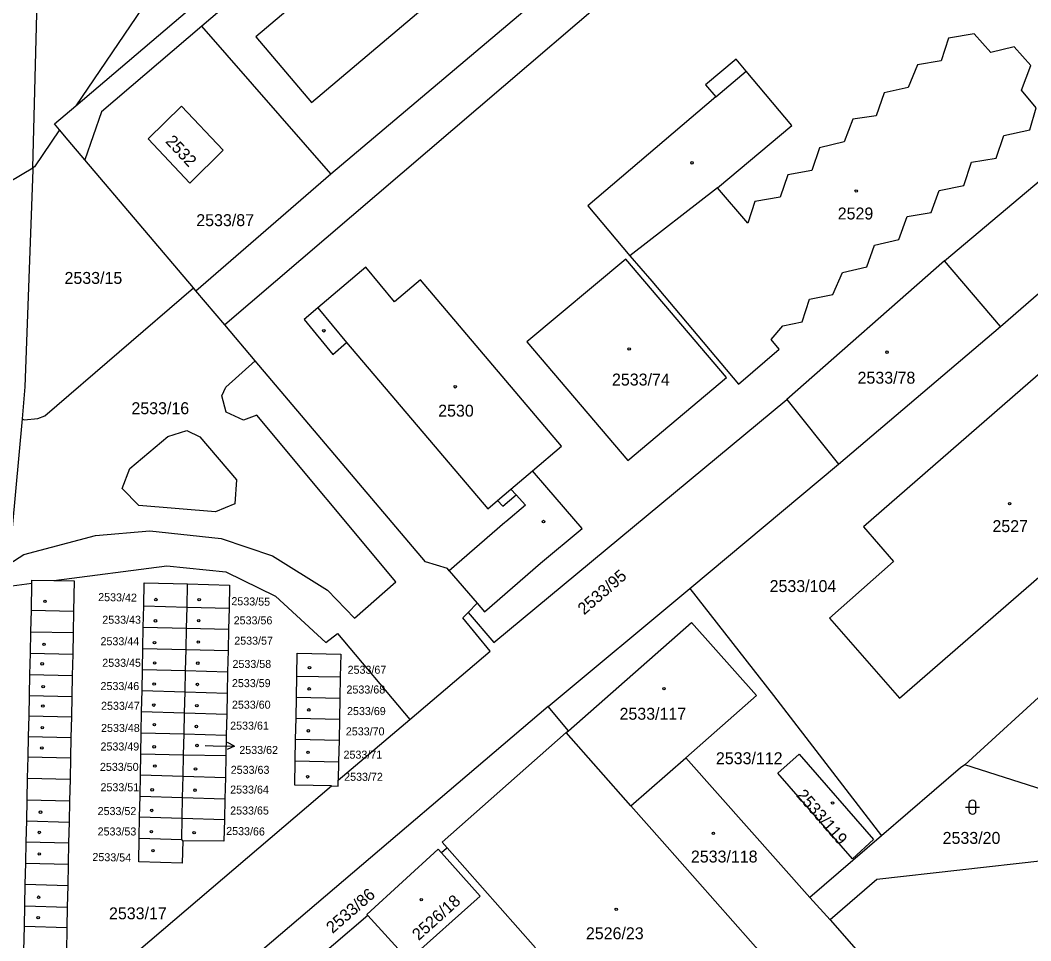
# Model space of a CAD drawing. Extents: x -527335 to -526256, y -1079142 to -1077809.
# Drawn here: x -527153.1 to -527009.3, y -1078313.2 to -1078182.2 of the extents above; entities that cross this region are included whole.
import ezdxf

# ---------------------------------------------------------------- set-up
doc = ezdxf.new("R2010")
doc.units = 0
for name, color, linetype in [('Vrstva 1', 7, 'Continuous'), ('Vrstva 2', 7, 'Continuous'), ('Vrstva 3', 7, 'Continuous'), ('Vrstva 4', 7, 'Continuous'), ('Vrstva 5', 7, 'Continuous'), ('Vrstva 7', 7, 'Continuous')]:
    doc.layers.add(name, color=color, linetype=linetype)

msp = doc.modelspace()

# ---------------------------------------------------------------- linework, layer by layer
at = {"layer": 'Vrstva 1'}
for p, q in [((-527145.19, -1078194.36), (-527021.08, -1078088.59)), ((-527075.98, -1078139.33), (-527127.29, -1078183.04)), ((-527108.95, -1078204.05), (-527057.85, -1078160.95)), ((-527108.95, -1078204.05), (-527127.29, -1078183.04)), ((-527021.59, -1078216.44), (-526994.58, -1078193.61)), ((-527128.49, -1078220.29), (-527143.91, -1078202.08)), ((-527013.64, -1078225.78), (-526986.9, -1078202.54)), ((-527168.74, -1078213.47), (-527151.32, -1078203.19)), ((-527128.12, -1078220.72), (-527108.95, -1078204.05)), ((-527021.59, -1078216.44), (-527044.03, -1078236.19)), ((-527013.64, -1078225.78), (-527021.59, -1078216.44)), ((-527128.12, -1078220.72), (-527128.49, -1078220.29)), ((-527124.03, -1078225.56), (-527128.12, -1078220.72)), ((-527036.7, -1078245.38), (-527013.64, -1078225.78)), ((-527018.73, -1078288.14), (-526960.09, -1078234.62)), ((-527044.03, -1078236.19), (-527036.7, -1078245.38)), ((-527057.86, -1078263.05), (-527036.7, -1078245.38)), ((-527092.08, -1078260.53), (-527088.09, -1078265.17)), ((-527155.03, -1078262.79), (-527151.46, -1078262.32)), ((-527151.54, -1078266.16), (-527151.46, -1078262.32)), ((-527129.38, -1078265.72), (-527129.3, -1078262.42)), ((-527078.01, -1078279.88), (-527057.86, -1078263.05)), ((-527135.61, -1078268.58), (-527135.55, -1078265.55)), ((-527135.55, -1078265.55), (-527129.38, -1078265.72)), ((-527129.45, -1078268.72), (-527129.38, -1078265.72)), ((-527129.38, -1078265.72), (-527123.41, -1078265.88)), ((-527123.41, -1078265.88), (-527123.48, -1078268.86)), ((-527089.37, -1078266.47), (-527088.09, -1078265.17)), ((-527151.61, -1078269.21), (-527151.54, -1078266.16)), ((-527151.54, -1078266.16), (-527145.52, -1078266.29)), ((-527145.52, -1078266.29), (-527145.59, -1078269.35)), ((-527135.67, -1078271.6), (-527135.61, -1078268.58)), ((-527135.61, -1078268.58), (-527129.45, -1078268.72)), ((-527129.52, -1078271.76), (-527129.45, -1078268.72)), ((-527129.45, -1078268.72), (-527123.48, -1078268.86)), ((-527123.48, -1078268.86), (-527123.54, -1078271.91)), ((-527151.68, -1078272.29), (-527151.61, -1078269.21)), ((-527151.61, -1078269.21), (-527145.59, -1078269.35)), ((-527145.59, -1078269.35), (-527145.65, -1078272.43)), ((-527135.73, -1078274.57), (-527135.67, -1078271.6)), ((-527135.67, -1078271.6), (-527129.52, -1078271.76)), ((-527129.59, -1078274.74), (-527129.52, -1078271.76)), ((-527129.52, -1078271.76), (-527123.54, -1078271.91)), ((-527123.54, -1078271.91), (-527123.61, -1078274.91)), ((-527151.75, -1078275.29), (-527151.68, -1078272.29)), ((-527151.68, -1078272.29), (-527145.65, -1078272.43)), ((-527145.65, -1078272.43), (-527145.72, -1078275.44)), ((-527135.79, -1078277.57), (-527135.73, -1078274.57)), ((-527135.73, -1078274.57), (-527129.59, -1078274.74)), ((-527129.66, -1078277.76), (-527129.59, -1078274.74)), ((-527129.59, -1078274.74), (-527123.61, -1078274.91)), ((-527151.81, -1078278.3), (-527151.75, -1078275.29)), ((-527151.75, -1078275.29), (-527145.72, -1078275.44)), ((-527145.72, -1078275.44), (-527145.78, -1078278.45)), ((-527123.61, -1078274.91), (-527123.67, -1078277.94)), ((-527113.83, -1078278.55), (-527113.78, -1078275.52)), ((-527113.78, -1078275.52), (-527107.58, -1078275.66)), ((-527107.58, -1078275.66), (-527107.64, -1078278.68)), ((-527135.85, -1078280.57), (-527135.79, -1078277.57)), ((-527135.79, -1078277.57), (-527129.66, -1078277.76)), ((-527151.87, -1078281.17), (-527151.81, -1078278.3)), ((-527151.81, -1078278.3), (-527145.78, -1078278.45)), ((-527145.78, -1078278.45), (-527145.84, -1078281.32)), ((-527129.73, -1078280.76), (-527129.66, -1078277.76)), ((-527129.66, -1078277.76), (-527123.67, -1078277.94)), ((-527123.67, -1078277.94), (-527123.74, -1078280.95)), ((-527113.88, -1078281.54), (-527113.83, -1078278.55)), ((-527113.83, -1078278.55), (-527107.64, -1078278.68)), ((-527107.64, -1078278.68), (-527107.7, -1078281.67)), ((-527075.11, -1078283.3), (-527078.01, -1078279.88)), ((-527151.94, -1078284.13), (-527151.87, -1078281.17)), ((-527151.87, -1078281.17), (-527145.84, -1078281.32)), ((-527145.84, -1078281.32), (-527145.91, -1078284.29)), ((-527135.9, -1078283.62), (-527135.85, -1078280.57)), ((-527135.85, -1078280.57), (-527129.73, -1078280.76)), ((-527129.8, -1078283.77), (-527129.73, -1078280.76)), ((-527129.73, -1078280.76), (-527123.74, -1078280.95)), ((-527123.74, -1078280.95), (-527123.8, -1078283.92)), ((-527113.94, -1078284.52), (-527113.88, -1078281.54)), ((-527113.88, -1078281.54), (-527107.7, -1078281.67)), ((-527107.87, -1078290.35), (-527097.7, -1078281.69)), ((-527107.7, -1078281.67), (-527107.76, -1078284.66)), ((-527075.43, -1078283.58), (-527075.11, -1078283.3)), ((-527152, -1078287), (-527151.94, -1078284.13)), ((-527151.94, -1078284.13), (-527145.91, -1078284.29)), ((-527145.91, -1078284.29), (-527145.97, -1078287.16)), ((-527135.96, -1078286.61), (-527135.9, -1078283.62)), ((-527135.9, -1078283.62), (-527129.8, -1078283.77)), ((-527129.87, -1078286.72), (-527129.8, -1078283.77)), ((-527129.8, -1078283.77), (-527123.8, -1078283.92)), ((-527123.8, -1078283.92), (-527123.87, -1078286.82)), ((-527113.99, -1078287.59), (-527113.94, -1078284.52)), ((-527113.94, -1078284.52), (-527107.76, -1078284.66)), ((-527107.76, -1078284.66), (-527107.82, -1078287.72)), ((-527066.22, -1078294.01), (-527075.43, -1078283.58)), ((-527152.07, -1078290.04), (-527152, -1078287)), ((-527152, -1078287), (-527145.97, -1078287.16)), ((-527145.97, -1078287.16), (-527146.03, -1078290.2)), ((-527136.02, -1078289.59), (-527135.96, -1078286.61)), ((-527135.96, -1078286.61), (-527129.87, -1078286.72)), ((-527129.94, -1078289.78), (-527129.87, -1078286.72)), ((-527129.87, -1078286.72), (-527123.87, -1078286.82)), ((-527123.87, -1078286.82), (-527123.93, -1078289.96)), ((-527113.99, -1078287.59), (-527107.82, -1078287.72)), ((-527107.82, -1078287.72), (-527107.87, -1078290.35)), ((-527066.22, -1078294.01), (-527058.42, -1078287.16)), ((-527058.42, -1078287.16), (-527040.76, -1078307.03)), ((-527152.14, -1078293.13), (-527152.07, -1078290.04)), ((-527152.07, -1078290.04), (-527146.03, -1078290.2)), ((-527146.03, -1078290.2), (-527146.1, -1078293.3)), ((-527136.08, -1078292.63), (-527136.02, -1078289.59)), ((-527136.02, -1078289.59), (-527129.94, -1078289.78)), ((-527130.01, -1078292.81), (-527129.94, -1078289.78)), ((-527129.94, -1078289.78), (-527123.93, -1078289.96)), ((-527123.93, -1078289.96), (-527124, -1078292.98)), ((-527152.2, -1078296.14), (-527152.14, -1078293.13)), ((-527152.14, -1078293.13), (-527146.1, -1078293.3)), ((-527146.1, -1078293.3), (-527146.16, -1078296.31)), ((-527136.14, -1078295.56), (-527136.08, -1078292.63)), ((-527136.08, -1078292.63), (-527130.01, -1078292.81)), ((-527130.08, -1078295.75), (-527130.01, -1078292.81)), ((-527130.01, -1078292.81), (-527124, -1078292.98)), ((-527124, -1078292.98), (-527124.06, -1078295.93)), ((-527152.27, -1078299.1), (-527152.2, -1078296.14)), ((-527152.2, -1078296.14), (-527146.16, -1078296.31)), ((-527146.16, -1078296.31), (-527146.23, -1078299.27)), ((-527136.19, -1078298.58), (-527136.14, -1078295.56)), ((-527136.14, -1078295.56), (-527130.08, -1078295.75)), ((-527130.15, -1078298.8), (-527130.08, -1078295.75)), ((-527130.08, -1078295.75), (-527124.06, -1078295.93)), ((-527152.34, -1078302.13), (-527152.27, -1078299.1)), ((-527152.27, -1078299.1), (-527146.23, -1078299.27)), ((-527136.19, -1078298.58), (-527130.15, -1078298.8)), ((-527129.99, -1078298.98), (-527130.15, -1078298.8)), ((-527030.55, -1078298.24), (-527040.76, -1078307.03)), ((-527146.23, -1078299.27), (-527146.29, -1078302.31)), ((-527079.8, -1078314.2), (-527092.36, -1078299.98)), ((-527152.4, -1078305.13), (-527152.34, -1078302.13)), ((-527152.34, -1078302.13), (-527146.29, -1078302.31)), ((-527146.29, -1078302.31), (-527146.36, -1078305.31)), ((-527152.47, -1078308.23), (-527152.4, -1078305.13)), ((-527152.4, -1078305.13), (-527146.36, -1078305.31)), ((-527146.36, -1078305.31), (-527146.42, -1078308.41)), ((-527040.76, -1078307.03), (-527037.9, -1078310.24)), ((-527152.53, -1078311.13), (-527152.47, -1078308.23)), ((-527152.47, -1078308.23), (-527146.42, -1078308.41)), ((-527146.42, -1078308.41), (-527146.49, -1078311.32)), ((-527152.53, -1078311.13), (-527146.49, -1078311.32))]:
    msp.add_line(p, q, dxfattribs=at)
for points in [[(-527151.32, -1078203.19), (-527149.15, -1078119.04), (-527147.89, -1078077.9), (-527146.9, -1078035.16), (-527147.21, -1078003.19)], [(-527021.08, -1078088.59), (-527032.67, -1078087.91), (-527048.92, -1078102.61), (-527126.32, -1078166.52), (-527145.19, -1078194.36)], [(-526994.58, -1078193.61), (-526995.55, -1078180.16), (-527023.46, -1078146.11), (-527026.79, -1078144.7), (-527030.6, -1078145.62), (-527124.03, -1078225.56)], [(-527073.25, -1078145.36), (-527119.6, -1078184.54), (-527111.69, -1078193.91), (-527065.33, -1078154.73), (-527073.25, -1078145.36)], [(-527127.29, -1078183.04), (-527141.57, -1078195.21), (-527143.91, -1078202.08)], [(-527018.88, -1078205.71), (-527017.76, -1078202.41), (-527014.28, -1078201.83), (-527013.18, -1078198.6), (-527009.48, -1078197.8), (-527008.56, -1078194.68), (-527010.67, -1078192.13), (-527009.31, -1078188.63), (-527011.7, -1078185.99), (-527015.02, -1078186.78), (-527017.41, -1078184.14), (-527021.05, -1078184.77), (-527022.1, -1078187.99), (-527025.47, -1078188.54), (-527026.77, -1078191.79), (-527030.19, -1078192.53), (-527031.34, -1078195.8), (-527034.66, -1078196.29), (-527035.89, -1078199.51), (-527039.38, -1078200.37), (-527040.49, -1078203.56), (-527043.9, -1078204.19), (-527044.98, -1078207.4), (-527048.61, -1078208), (-527049.6, -1078211.09), (-527053.92, -1078206.07), (-527043.32, -1078197.16), (-527049.81, -1078189.45), (-527051.27, -1078187.72), (-527055.6, -1078191.37), (-527054.14, -1078193.1), (-527072.36, -1078208.61), (-527066.4, -1078215.71), (-527063.27, -1078219.32), (-527050.92, -1078233.97), (-527045.12, -1078229.03), (-527046.26, -1078227.64), (-527044.59, -1078225.71), (-527041.86, -1078225.11), (-527040.83, -1078221.89), (-527037.48, -1078221.21), (-527036.11, -1078218.11), (-527032.68, -1078217.29), (-527031.57, -1078214.19), (-527028.13, -1078213.4), (-527026.91, -1078210.12), (-527023.49, -1078209.55), (-527022.35, -1078206.41), (-527018.88, -1078205.71)], [(-527147.53, -1078197.81), (-527148.24, -1078196.96), (-527145.19, -1078194.36)], [(-527130.16, -1078194.44), (-527134.92, -1078199.06), (-527128.97, -1078205.37), (-527124.24, -1078200.67), (-527130.16, -1078194.44)], [(-527147.53, -1078197.81), (-527151.07, -1078203.04), (-527151.32, -1078203.19)], [(-527143.91, -1078202.08), (-527146.31, -1078199.25), (-527147.53, -1078197.81)], [(-527151.32, -1078203.19), (-527151.33, -1078203.5), (-527152.45, -1078234.37), (-527152.87, -1078238.94)], [(-527066.97, -1078216.19), (-527081.03, -1078227.97), (-527066.68, -1078244.84), (-527052.61, -1078233.06), (-527066.97, -1078216.19)], [(-527088.09, -1078265.17), (-527087.05, -1078266.38), (-527079.07, -1078259.48), (-527073.18, -1078254.52), (-527078.17, -1078248.69), (-527080.22, -1078246.3), (-527076.09, -1078242.8), (-527096.17, -1078219.13), (-527099.86, -1078222.26), (-527103.94, -1078217.32), (-527110.79, -1078223.12), (-527112.74, -1078224.77), (-527108.62, -1078229.78), (-527106.7, -1078228.08), (-527086.6, -1078251.71), (-527085.21, -1078250.53), (-527084.47, -1078251.37), (-527082.56, -1078249.74), (-527081.22, -1078251.23), (-527084.03, -1078253.58), (-527084.16, -1078253.69), (-527092.08, -1078260.53)], [(-527152.87, -1078238.94), (-527152.57, -1078239.08), (-527150.64, -1078238.89), (-527149.6, -1078238.5), (-527128.49, -1078220.29)], [(-527092.08, -1078260.53), (-527092.34, -1078260.22), (-527095.48, -1078259.26), (-527119.71, -1078230.66), (-527124.03, -1078225.56)], [(-527028.01, -1078278.65), (-526982.22, -1078238.91), (-526992.1, -1078227.53), (-527001.43, -1078235.36), (-527005.72, -1078230.41), (-527033.14, -1078254.27), (-527028.87, -1078259.23), (-527037.98, -1078267.3), (-527028.01, -1078278.65)], [(-527089.37, -1078266.47), (-527085.73, -1078270.77), (-527044.03, -1078236.19)], [(-527152.87, -1078238.94), (-527154.74, -1078259.62), (-527154.85, -1078260.85)], [(-527148.36, -1078261.92), (-527132.28, -1078259.83), (-527123.87, -1078260.69), (-527116.82, -1078264.18), (-527109.65, -1078270.74), (-527107.97, -1078269.47), (-527097.7, -1078281.69)], [(-527151.46, -1078262.32), (-527151.45, -1078261.88), (-527148.36, -1078261.92)], [(-527148.36, -1078261.92), (-527145.43, -1078261.96), (-527145.52, -1078266.29)], [(-527135.55, -1078265.55), (-527135.49, -1078262.25), (-527129.3, -1078262.42)], [(-527129.3, -1078262.42), (-527123.34, -1078262.59), (-527123.41, -1078265.88)], [(-527057.86, -1078263.05), (-527045.96, -1078278.29), (-527030.55, -1078298.24)], [(-527097.7, -1078281.69), (-527086.26, -1078271.99), (-527090.15, -1078267.26), (-527089.37, -1078266.47)], [(-527075.11, -1078283.3), (-527057.6, -1078267.89), (-527048.34, -1078278.31), (-527058.42, -1078287.16)], [(-527113.78, -1078275.52), (-527113.72, -1078272.27), (-527107.51, -1078272.43), (-527107.58, -1078275.66)], [(-527078.01, -1078279.88), (-527149.04, -1078340.4), (-527152.71, -1078341.14), (-527153.16, -1078344.42), (-527154.22, -1078350.96), (-527154.21, -1078352.81)], [(-527092.36, -1078299.98), (-527093.08, -1078299.16), (-527075.43, -1078283.58)], [(-527108.84, -1078291.17), (-527114.05, -1078291.06), (-527113.99, -1078287.59)], [(-527031.69, -1078298.77), (-527034.72, -1078301.52), (-527045.34, -1078289.33), (-527042.31, -1078286.66), (-527031.69, -1078298.77)], [(-527018.73, -1078288.14), (-527019.33, -1078288.58), (-527030.55, -1078298.24)], [(-526991.13, -1078293.46), (-526996.39, -1078293.96), (-526999.54, -1078294.26), (-527018.73, -1078288.14)], [(-527108.84, -1078291.17), (-527107.89, -1078291.19), (-527107.87, -1078290.35)], [(-527157.99, -1078333.04), (-527157.02, -1078332.22), (-527108.84, -1078291.17)], [(-527041.68, -1078321.81), (-527061.79, -1078299.03), (-527066.22, -1078294.01)], [(-527124.06, -1078295.93), (-527124.13, -1078299.02), (-527129.99, -1078298.98)], [(-527129.99, -1078298.98), (-527130.08, -1078302.17), (-527136.26, -1078301.98), (-527136.19, -1078298.58)], [(-527093.17, -1078300.67), (-527093.64, -1078300.14), (-527103.79, -1078309.46), (-527103.65, -1078309.62)], [(-527092.36, -1078299.98), (-527092.46, -1078300.07), (-527093.17, -1078300.67)], [(-527093.17, -1078300.67), (-527087.7, -1078306.87), (-527097.86, -1078315.97), (-527103.65, -1078309.62)], [(-527000.09, -1078301), (-527004.9, -1078305.04), (-527006.83, -1078302.75), (-527007.63, -1078301.84), (-527031.23, -1078304.49), (-527037.9, -1078310.24)], [(-527103.65, -1078309.62), (-527113.42, -1078317.97), (-527124.23, -1078327.2)], [(-527037.9, -1078310.24), (-527033.83, -1078314.82), (-527041.68, -1078321.81)], [(-527146.49, -1078311.32), (-527146.56, -1078314.81), (-527152.61, -1078314.62), (-527152.53, -1078311.13)]]:
    msp.add_lwpolyline(points, dxfattribs=at)
at = {"layer": 'Vrstva 3'}
for p, q in [((-527018.63, -1078294.18), (-527016.63, -1078294.18)), ((-527018.13, -1078293.68), (-527018.13, -1078294.68)), ((-527017.13, -1078294.68), (-527017.13, -1078293.68))]:
    msp.add_line(p, q, dxfattribs=at)
for centre, start, end in [((-527017.63, -1078293.68), 0, 180), ((-527017.63, -1078294.68), 180, 359.9879)]:
    msp.add_arc(centre, 0.5, start, end, dxfattribs=at)
at = {"layer": 'Vrstva 4'}
for p, q in [((-527054.14, -1078193.1), (-527049.81, -1078189.45)), ((-527053.92, -1078206.07), (-527066.4, -1078215.71)), ((-527110.79, -1078223.12), (-527106.7, -1078228.08)), ((-527123.89, -1078234.43), (-527119.71, -1078230.66)), ((-527124.43, -1078235.67), (-527123.89, -1078234.43)), ((-527123.84, -1078237.98), (-527124.43, -1078235.67)), ((-527121.35, -1078239.1), (-527123.84, -1078237.98)), ((-527119.46, -1078238.39), (-527121.35, -1078239.1)), ((-527099.7, -1078262.11), (-527119.46, -1078238.39)), ((-527137.51, -1078246.01), (-527132.14, -1078241.43)), ((-527132.14, -1078241.43), (-527129.43, -1078240.6)), ((-527129.43, -1078240.6), (-527127.57, -1078241.48)), ((-527127.57, -1078241.48), (-527122.37, -1078247.62)), ((-527138.63, -1078248.82), (-527137.51, -1078246.01)), ((-527083.3, -1078248.91), (-527080.22, -1078246.3)), ((-527136.23, -1078251.24), (-527138.63, -1078248.82)), ((-527122.37, -1078247.62), (-527122.57, -1078251.03)), ((-527085.21, -1078250.53), (-527083.3, -1078248.91)), ((-527082.56, -1078249.74), (-527083.3, -1078248.91)), ((-527125.36, -1078252.17), (-527136.23, -1078251.24)), ((-527122.57, -1078251.03), (-527125.36, -1078252.17)), ((-527152.61, -1078258.22), (-527142.42, -1078255.53)), ((-527142.42, -1078255.53), (-527134.69, -1078254.87)), ((-527134.69, -1078254.87), (-527124.53, -1078255.97)), ((-527124.53, -1078255.97), (-527117.21, -1078258.41)), ((-527154.74, -1078259.62), (-527152.61, -1078258.22)), ((-527117.21, -1078258.41), (-527109.4, -1078263.29)), ((-527105.58, -1078267.28), (-527099.7, -1078262.11)), ((-527109.4, -1078263.29), (-527105.58, -1078267.28))]:
    msp.add_line(p, q, dxfattribs=at)
at = {"layer": 'Vrstva 5'}
for centre in [(-527057.53, -1078202.49), (-527034.17, -1078206.5), (-527109.92, -1078226.39), (-527066.48, -1078228.97), (-527029.78, -1078229.43), (-527091.23, -1078234.36), (-527012.35, -1078250.98), (-527078.67, -1078253.54), (-527149.6, -1078264.88), (-527133.82, -1078264.64), (-527127.66, -1078264.66), (-527133.88, -1078267.67), (-527127.73, -1078267.64), (-527149.73, -1078271.02), (-527134.02, -1078270.76), (-527127.79, -1078270.69), (-527150, -1078273.79), (-527134, -1078273.66), (-527127.86, -1078273.69), (-527111.96, -1078274.32), (-527149.86, -1078277.04), (-527134.06, -1078276.66), (-527127.92, -1078276.72), (-527112.01, -1078277.35), (-527061.53, -1078277.32), (-527149.91, -1078279.79), (-527134.12, -1078279.66), (-527127.99, -1078279.73), (-527112.06, -1078280.34), (-527149.99, -1078282.88), (-527134.04, -1078282.44), (-527128.05, -1078282.7), (-527112.12, -1078283.32), (-527150.05, -1078285.75), (-527134.06, -1078285.6), (-527127.98, -1078285.41), (-527112.17, -1078286.39), (-527133.97, -1078288.33), (-527128.18, -1078288.74), (-527112.23, -1078289.86), (-527134.35, -1078291.72), (-527128.25, -1078291.76), (-527037.54, -1078293.6), (-527150.24, -1078294.9), (-527134.41, -1078294.65), (-527150.41, -1078297.78), (-527134.46, -1078297.67), (-527128.38, -1078297.8), (-527054.49, -1078297.91), (-527150.41, -1078300.84), (-527134.24, -1078300.36), (-527150.5, -1078307), (-527096.06, -1078307.34), (-527068.32, -1078308.73), (-527150.57, -1078309.91)]:
    msp.add_circle(centre, 0.175, dxfattribs=at)
at = {"layer": 'Vrstva 7'}
for p, q in [((-527126.83, -1078285.43), (-527125.65, -1078285.45)), ((-527125.65, -1078285.45), (-527122.65, -1078285.5)), ((-527122.65, -1078285.5), (-527123.66, -1078285.99)), ((-527122.65, -1078285.5), (-527123.64, -1078284.98))]:
    msp.add_line(p, q, dxfattribs=at)

# ---------------------------------------------------------------- texts
at = {"layer": 'Vrstva 2'}
for s, height, rotation, p in [('2532', 1.7, 313, (-527132.56, -1078199.51)), ('2533/95', 1.7, 41, (-527072.89, -1078266.9)), ('2533/42', 1.14, 359, (-527142.04, -1078264.85)), ('2533/42', 1.14, 359, (-527142.04, -1078264.85)), ('2533/55', 1.14, 359, (-527123.09, -1078265.43)), ('2533/55', 1.14, 359, (-527123.09, -1078265.43)), ('2533/119', 1.7, 311, (-527042.78, -1078292.54)), ('2533/66', 1.14, 359, (-527123.83, -1078298.13)), ('2533/66', 1.14, 359, (-527123.83, -1078298.13)), ('2533/54', 1.14, 359, (-527142.86, -1078301.84)), ('2533/86', 1.7, 41, (-527108.68, -1078312.24)), ('2526/18', 1.7, 42, (-527096.43, -1078313.25))]:
    msp.add_text(s, height=height, rotation=rotation, dxfattribs=at).set_placement(p)
for s, height, p in [('2533/87', 1.7, (-527128.07, -1078211.5)), ('2529', 1.7, (-527036.8, -1078210.55)), ('2533/15', 1.7, (-527146.82, -1078219.72)), ('2533/74', 1.7, (-527068.92, -1078234.18)), ('2533/78', 1.7, (-527033.98, -1078233.92)), ('2533/16', 1.7, (-527137.3, -1078238.26)), ('2530', 1.7, (-527093.65, -1078238.61)), ('2527', 1.7, (-527014.79, -1078255.04)), ('2533/104', 1.7, (-527046.49, -1078263.57)), ('2533/43', 1.139, (-527141.45, -1078268.08)), ('2533/43', 1.139, (-527141.45, -1078268.08)), ('2533/56', 1.139, (-527122.75, -1078268.17)), ('2533/56', 1.139, (-527122.75, -1078268.17)), ('2533/44', 1.139, (-527141.7, -1078271.14)), ('2533/44', 1.139, (-527141.7, -1078271.14)), ('2533/57', 1.139, (-527122.67, -1078271.06)), ('2533/57', 1.139, (-527122.67, -1078271.06)), ('2533/45', 1.139, (-527141.45, -1078274.21)), ('2533/45', 1.139, (-527141.45, -1078274.21)), ('2533/58', 1.139, (-527122.92, -1078274.37)), ('2533/58', 1.139, (-527122.92, -1078274.37)), ('2533/67', 1.139, (-527106.54, -1078275.2)), ('2533/67', 1.139, (-527106.54, -1078275.2)), ('2533/59', 1.139, (-527123, -1078277.1)), ('2533/59', 1.139, (-527123, -1078277.1)), ('2533/46', 1.139, (-527141.7, -1078277.52)), ('2533/46', 1.139, (-527141.7, -1078277.52)), ('2533/68', 1.139, (-527106.7, -1078278.01)), ('2533/68', 1.139, (-527106.7, -1078278.01)), ('2533/60', 1.139, (-527123, -1078280.17)), ('2533/60', 1.139, (-527123, -1078280.17)), ('2533/47', 1.139, (-527141.62, -1078280.33)), ('2533/47', 1.139, (-527141.62, -1078280.33)), ('2533/69', 1.139, (-527106.62, -1078281.08)), ('2533/69', 1.139, (-527106.62, -1078281.08)), ('2533/117', 1.7, (-527067.85, -1078281.74)), ('2533/61', 1.139, (-527123.25, -1078283.15)), ('2533/61', 1.139, (-527123.25, -1078283.15)), ('2533/48', 1.139, (-527141.62, -1078283.48)), ('2533/48', 1.139, (-527141.62, -1078283.48)), ('2533/70', 1.139, (-527106.79, -1078283.97)), ('2533/70', 1.139, (-527106.79, -1078283.97)), ('2533/49', 1.139, (-527141.7, -1078286.12)), ('2533/49', 1.139, (-527141.7, -1078286.12)), ('2533/62', 1.139, (-527121.95, -1078286.61)), ('2533/71', 1.139, (-527107.12, -1078287.28)), ('2533/71', 1.139, (-527107.12, -1078287.28)), ('2533/112', 1.7, (-527054.13, -1078288.07)), ('2533/50', 1.139, (-527141.78, -1078289.02)), ('2533/50', 1.139, (-527141.78, -1078289.02)), ('2533/63', 1.139, (-527123.17, -1078289.44)), ('2533/63', 1.139, (-527123.17, -1078289.44)), ('2533/72', 1.139, (-527107.03, -1078290.43)), ('2533/72', 1.139, (-527107.03, -1078290.43)), ('2533/51', 1.139, (-527141.7, -1078291.92)), ('2533/51', 1.139, (-527141.7, -1078291.92)), ('2533/64', 1.139, (-527123.25, -1078292.25)), ('2533/64', 1.139, (-527123.25, -1078292.25)), ('2533/52', 1.139, (-527142.11, -1078295.31)), ('2533/52', 1.139, (-527142.11, -1078295.31)), ('2533/65', 1.139, (-527123.25, -1078295.23)), ('2533/65', 1.139, (-527123.25, -1078295.23)), ('2533/53', 1.139, (-527142.11, -1078298.21)), ('2533/53', 1.139, (-527142.11, -1078298.21)), ('2533/20', 1.7, (-527021.87, -1078299.41)), ('2533/118', 1.7, (-527057.69, -1078302.06)), ('2533/17', 1.7, (-527140.49, -1078310.14)), ('2526/23', 1.7, (-527072.63, -1078312.98))]:
    msp.add_text(s, height=height, dxfattribs=at).set_placement(p)

doc.saveas('drawing.dxf')
